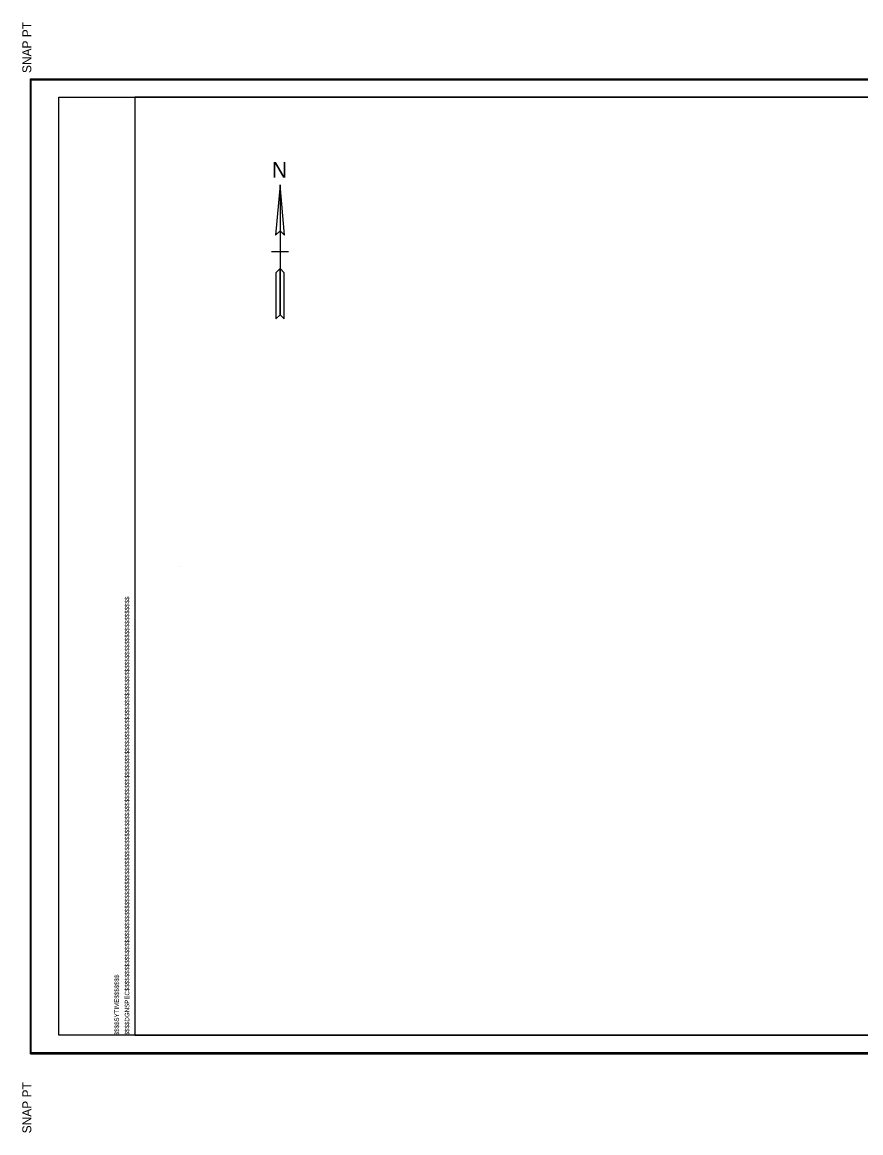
# Model space of a CAD drawing. Extents: x -200 to 1683011, y -325 to 519568.
# Drawn here: x 1679258 to 1681134, y 517081 to 519568 of the extents above; entities that cross this region are included whole.
import ezdxf

# ---------------------------------------------------------------- set-up
doc = ezdxf.new("R2010")
doc.units = 0
for name, color, linetype in [('DESIGN - CENTERLINE - Proposed Text', 7, 'Continuous'), ('DESIGN - SCRATCH - User 1', 7, 'Continuous'), ('DESIGN - SHEET - Corner Text', 7, 'Continuous'), ('DESIGN - SHEET - Linework', 7, 'Continuous'), ('DESIGN - SHEET - Plot Shape', 7, 'Continuous')]:
    doc.layers.add(name, color=color, linetype=linetype)

msp = doc.modelspace()

# ---------------------------------------------------------------- linework, layer by layer
at = {"layer": 'DESIGN - CENTERLINE - Proposed Text'}
for p, q in [((1679834.4, 519053.4), (1679815.5, 519053.4)), ((1679853.3, 519053.4), (1679834.4, 519053.4))]:
    msp.add_line(p, q, dxfattribs=at)
msp.add_lwpolyline([(1679834.4, 519203.4), (1679824.6, 519090.8), (1679834.4, 519100.6), (1679844.2, 519090.8), (1679834.4, 519203.4), (1679834.4, 518912.5), (1679843.5, 518903.4), (1679843.5, 519006.9), (1679834.4, 519016), (1679825.3, 519006.9), (1679825.3, 518903.4), (1679834.4, 518912.5)], dxfattribs=at)
for points in [[(1679834.4, 519100.6), (1679844.2, 519090.8), (1679834.4, 519203.4)], [(1679825.3, 518903.4), (1679834.4, 518912.5), (1679834.4, 519016), (1679825.3, 519006.9)]]:
    msp.add_lwpolyline(points, close=True, dxfattribs=at)
at = {"layer": 'DESIGN - SCRATCH - User 1'}
msp.add_line((1679609.7, 518349.6), (1679609.7, 518349.6), dxfattribs=at)
at = {"layer": 'DESIGN - SHEET - Linework'}
for p, q in [((1679275.8, 517258.2), (1679275.8, 519441)), ((1679275.8, 519441), (1682679.8, 519441)), ((1679275.8, 517258.2), (1682679.8, 517258.2))]:
    msp.add_line(p, q, dxfattribs=at)
msp.add_lwpolyline([(1679509.7, 519399.6), (1679509.7, 517299.6), (1682658.1, 517299.6), (1682658.1, 519399.6), (1679509.7, 519399.6)], dxfattribs=at)
at = {"layer": 'DESIGN - SHEET - Plot Shape'}
for points in [[(1679277.8, 519439), (1682677.8, 519439), (1682677.8, 517260.2), (1679277.8, 517260.2)], [(1679339.6, 519399.6), (1682658.1, 519399.6), (1682658.1, 517299.6), (1679339.6, 517299.6)]]:
    msp.add_lwpolyline(points, close=True, dxfattribs=at)

# ---------------------------------------------------------------- texts
at = {"layer": 'DESIGN - CENTERLINE - Proposed Text'}
msp.add_text('N', height=35.4, dxfattribs=at).set_placement((1679816.3, 519219.5))
at = {"layer": 'DESIGN - SHEET - Corner Text'}
for s, height, p in [('  SNAP PT', 20, (1679277.8, 519439)), ('$$$$DGNSPEC$$$$$$$$$$$$$$$$$$$$$$$$$$$$$$$$$$$$$$$$$$$$$$$$$$$$$$$$$$$$$$$$$$$$$$$$$$$$$$$$$$$$$$$$$$$$$$$$$$$$$$$$$$$$$$$$$$$', 10.0002, (1679497.1, 517299.6)), ('$$$$SYTIME$$$$$$$', 10, (1679473.9, 517299.6)), ('SNAP PT  ', 20, (1679277.8, 517080.2))]:
    msp.add_text(s, height=height, rotation=90, dxfattribs=at).set_placement(p)

doc.saveas('drawing.dxf')
